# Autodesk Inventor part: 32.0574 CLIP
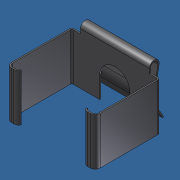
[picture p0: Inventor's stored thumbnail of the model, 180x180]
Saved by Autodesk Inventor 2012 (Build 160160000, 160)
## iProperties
Created: 2013-04
Part Number: 32.0574 CLIP
Material: Stainless Steel
Document SubType Name: Modeling
Designer: Admin
Density: 8.08 g/cm^3
Mass: 9.87954 g
Surface Area: 50.4509 cm^2
Volume: 1.22272 cm^3
Author: Admin
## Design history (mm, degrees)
feature "Base1"
body "Solid1"
